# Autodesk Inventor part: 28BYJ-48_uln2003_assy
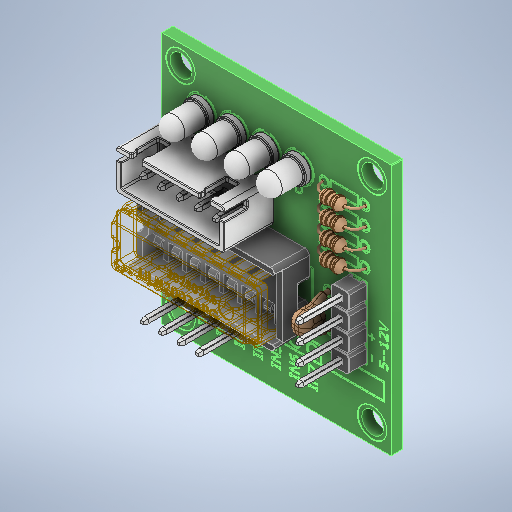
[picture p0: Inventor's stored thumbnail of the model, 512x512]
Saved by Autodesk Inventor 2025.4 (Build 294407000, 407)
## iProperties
Created: 2025-08
Part Number: 28BYJ-48_uln2003_assy
Material: Generic
Document SubType Name: Modeling
Designer: Marcio Valenzuela
Density: 1 g/cm^3
Appearance: Default
Title: 28BYJ-48_uln2003_assy.stp
Sending System: SIEMENS PLM Software NX 10.0
Preprocessor: ST-DEVELOPER v16
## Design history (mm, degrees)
feature "PIN (2)" [Base]
feature "BRK" [Base]
feature "Base7"
feature "PIN (2):1" [Base]
feature "PIN (2):2" [Base]
feature "PIN (2):3" [Base]
feature "PIN (2):4" [Base]
feature "Base12"
feature "PIN (2):5" [Base]
feature "PIN (2):6" [Base]
feature "Base15"
feature "BRK:1" [Base]
feature "PIN (2):7" [Base]
feature "Base18"
feature "Base19"
feature "Base20"
feature "Base31"
feature "Base32"
feature "Base33"
feature "Base34"
feature "Base35"
feature "Base36"
feature "Composite1"
body "Solid11"
body "Solid1"
body "Solid2"
body "Solid15"
body "Solid3"
body "Solid4"
body "Solid5"
body "Solid6"
body "Solid16"
body "Solid7"
body "Solid8"
body "Solid17"
body "Solid9"
body "Solid10"
body "Solid18"
body "Solid19"
body "Solid20"
body "Solid31"
body "Solid32"
body "Solid33"
body "Solid34"
body "Solid35"
body "Solid36"
body "Srf1"
